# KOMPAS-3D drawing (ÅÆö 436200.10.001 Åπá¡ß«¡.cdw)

Referenced files in C:\Users\ptitsin\Desktop\Блок ПД 476 (160т)\: 76.80.041-2 Пуансон.cdw
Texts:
  Цементировать h 1...1.5 мм.; 54...58 HRCэ
  Полировать, х10, полировать
  Острые кромки притупить  1 мм.
  H14, h14,  IT 14/2.
  CONTINUOUS_RGB_255_0_0_THICK_0.25
  СONTINUOUS_RGB_0_0_0_THICK_0.18
  ACAD_ISO02W100_RGB_0_0_0_SC_1_THICK_0.18
  CONTINUOUS_RGB_0_0_0_THICK_0.18
  ACAD_ISO10W100_RGB_0_0_0_SC_1_THICK_0.18
  POLYLINE_STYLE_0.50_RGB_0_0_0
  GOST2.303 6_RGB_0_0_0_SC_1_THICK_0.18
  невидимая2_RGB_0_0_0_SC_1_THICK_0.6
  невидимая2_RGB_255_0_0_SC_1_THICK_0.25
  GOST2.303 6_RGB_255_0_0_SC_1_THICK_0.25
  GOST2.303 5_RGB_255_0_0_SC_1_THICK_0.25
  ПТФ 436200.10.001
  Пуансон
  Сталь 12ХН3А ГОСТ 4543-71
  ООО "ЗАВОД МАРКОН"
  ПТФ 436200.10.001-
Dimensions and other numbers on the sheet: 20; 10; 30; 50; 220; 3 отв.; 25; 150; 160; 260; 5; 140; 180; 0,03; 45; 15; 22,5; 4 отв.; 1; 16 отв.; 0.1; 6,3; 4; 1:1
